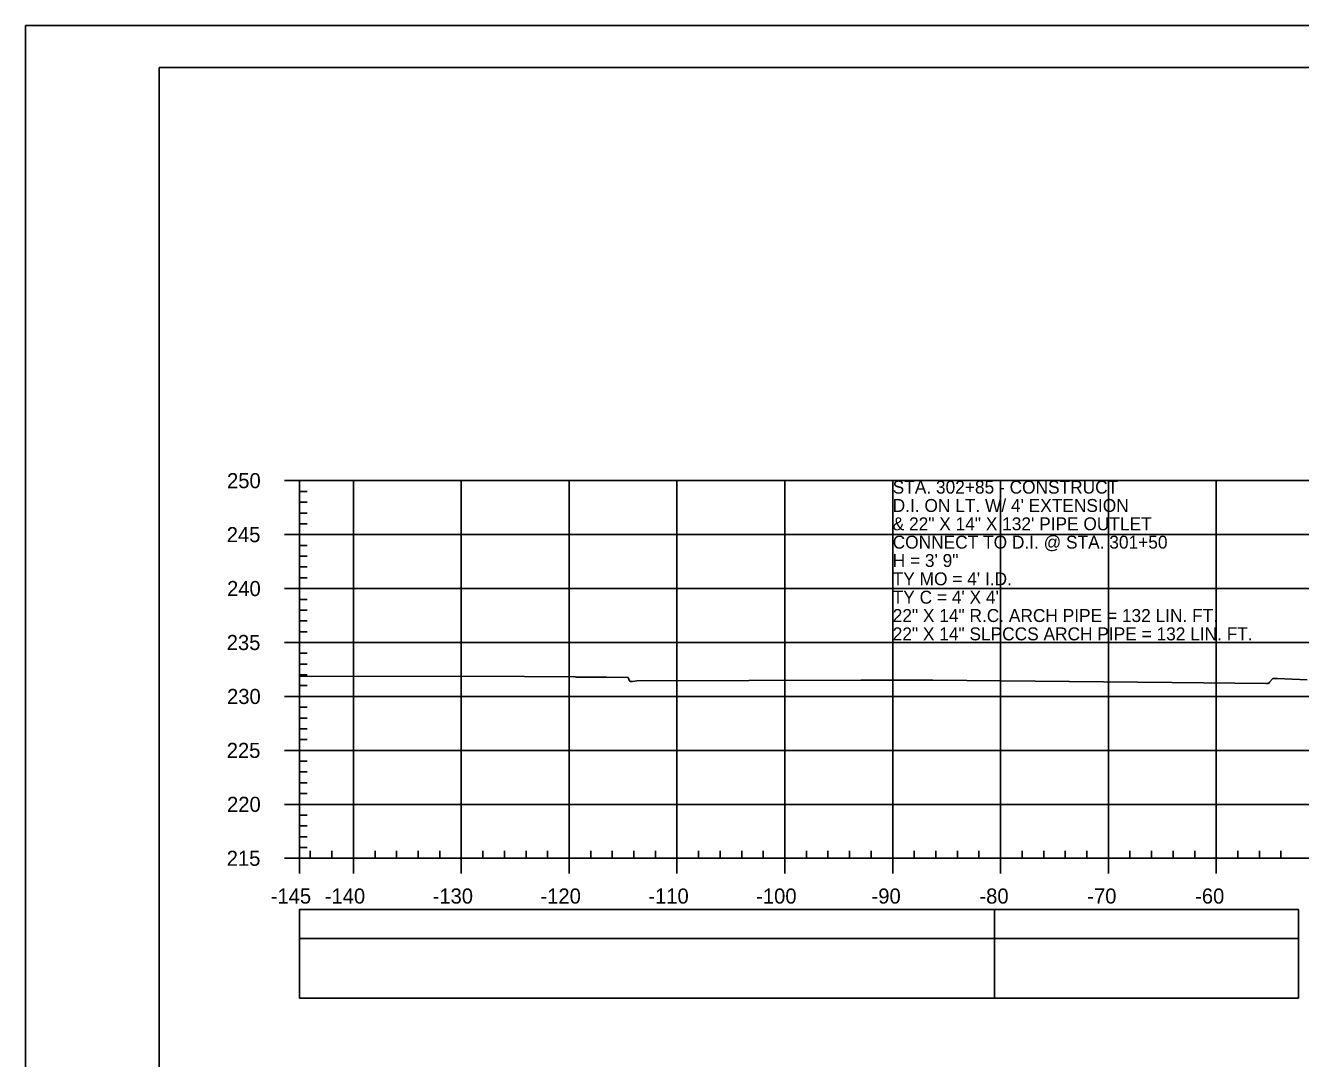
# Model space of a CAD drawing. Extents: x 1386544 to 1388153, y 379785 to 390999.
# Drawn here: x 1386544.5 to 1386662.7, y 384609.5 to 384705.3 of the extents above; entities that cross this region are included whole.
import ezdxf

# ---------------------------------------------------------------- set-up
doc = ezdxf.new("R2010")
doc.units = 0
for name, color, linetype in [('R_Axis', 7, 'Continuous'), ('R_Axis Annot', 7, 'Continuous'), ('R_Border', 7, 'Continuous'), ('R_Exist Surface', 7, 'Continuous'), ('R_Grid', 7, 'Continuous'), ('R_No Plot', 7, 'Continuous'), ('R_Striping', 7, 'Continuous'), ('R_Water Annot', 7, 'Continuous')]:
    doc.layers.add(name, color=color, linetype=linetype)

msp = doc.modelspace()

# ---------------------------------------------------------------- linework, layer by layer
at = {"layer": 'R_Axis'}
for p, q in [((1386568.47, 384663.09), (1386569.87, 384663.09)), ((1386569.87, 384628.09), (1386569.87, 384663.09)), ((1386569.87, 384662.09), (1386570.57, 384662.09)), ((1386569.87, 384661.09), (1386570.57, 384661.09)), ((1386569.87, 384660.09), (1386570.57, 384660.09)), ((1386568.47, 384658.09), (1386569.87, 384658.09)), ((1386569.87, 384659.09), (1386570.57, 384659.09)), ((1386569.87, 384657.09), (1386570.57, 384657.09)), ((1386569.87, 384656.09), (1386570.57, 384656.09)), ((1386569.87, 384655.09), (1386570.57, 384655.09)), ((1386569.87, 384654.09), (1386570.57, 384654.09)), ((1386568.47, 384653.09), (1386569.87, 384653.09)), ((1386569.87, 384652.09), (1386570.57, 384652.09)), ((1386569.87, 384651.09), (1386570.57, 384651.09)), ((1386569.87, 384650.09), (1386570.57, 384650.09)), ((1386569.87, 384649.09), (1386570.57, 384649.09)), ((1386568.47, 384648.09), (1386569.87, 384648.09)), ((1386569.87, 384647.09), (1386570.57, 384647.09)), ((1386569.87, 384646.09), (1386570.57, 384646.09)), ((1386569.87, 384645.09), (1386570.57, 384645.09)), ((1386569.87, 384644.09), (1386570.57, 384644.09)), ((1386568.47, 384643.09), (1386569.87, 384643.09)), ((1386569.87, 384642.09), (1386570.57, 384642.09)), ((1386569.87, 384641.09), (1386570.57, 384641.09)), ((1386569.87, 384640.09), (1386570.57, 384640.09)), ((1386569.87, 384639.09), (1386570.57, 384639.09)), ((1386568.47, 384638.09), (1386569.87, 384638.09)), ((1386569.87, 384637.09), (1386570.57, 384637.09)), ((1386569.87, 384636.09), (1386570.57, 384636.09)), ((1386569.87, 384635.09), (1386570.57, 384635.09)), ((1386569.87, 384634.09), (1386570.57, 384634.09)), ((1386568.47, 384633.09), (1386569.87, 384633.09)), ((1386569.87, 384632.09), (1386570.57, 384632.09)), ((1386569.87, 384631.09), (1386570.57, 384631.09)), ((1386569.87, 384630.09), (1386570.57, 384630.09)), ((1386569.87, 384629.09), (1386570.57, 384629.09)), ((1386569.87, 384628.09), (1386569.87, 384628.79)), ((1386570.87, 384628.09), (1386570.87, 384628.79)), ((1386572.87, 384628.09), (1386572.87, 384628.79)), ((1386576.87, 384628.09), (1386576.87, 384628.79)), ((1386578.87, 384628.09), (1386578.87, 384628.79)), ((1386580.87, 384628.09), (1386580.87, 384628.79)), ((1386582.87, 384628.09), (1386582.87, 384628.79)), ((1386586.87, 384628.09), (1386586.87, 384628.79)), ((1386588.87, 384628.09), (1386588.87, 384628.79)), ((1386590.87, 384628.09), (1386590.87, 384628.79)), ((1386592.87, 384628.09), (1386592.87, 384628.79)), ((1386596.87, 384628.09), (1386596.87, 384628.79)), ((1386598.87, 384628.09), (1386598.87, 384628.79)), ((1386600.87, 384628.09), (1386600.87, 384628.79)), ((1386602.87, 384628.09), (1386602.87, 384628.79)), ((1386606.87, 384628.09), (1386606.87, 384628.79)), ((1386608.87, 384628.09), (1386608.87, 384628.79)), ((1386610.87, 384628.09), (1386610.87, 384628.79)), ((1386612.87, 384628.09), (1386612.87, 384628.79)), ((1386616.87, 384628.09), (1386616.87, 384628.79)), ((1386618.87, 384628.09), (1386618.87, 384628.79)), ((1386620.87, 384628.09), (1386620.87, 384628.79)), ((1386622.87, 384628.09), (1386622.87, 384628.79)), ((1386626.87, 384628.09), (1386626.87, 384628.79)), ((1386628.87, 384628.09), (1386628.87, 384628.79)), ((1386630.87, 384628.09), (1386630.87, 384628.79)), ((1386632.87, 384628.09), (1386632.87, 384628.79)), ((1386636.87, 384628.09), (1386636.87, 384628.79)), ((1386638.87, 384628.09), (1386638.87, 384628.79)), ((1386640.87, 384628.09), (1386640.87, 384628.79)), ((1386642.87, 384628.09), (1386642.87, 384628.79)), ((1386646.87, 384628.09), (1386646.87, 384628.79)), ((1386648.87, 384628.09), (1386648.87, 384628.79)), ((1386650.87, 384628.09), (1386650.87, 384628.79)), ((1386652.87, 384628.09), (1386652.87, 384628.79)), ((1386656.87, 384628.09), (1386656.87, 384628.79)), ((1386658.87, 384628.09), (1386658.87, 384628.79)), ((1386660.87, 384628.09), (1386660.87, 384628.79)), ((1386568.47, 384628.09), (1386569.87, 384628.09)), ((1386569.87, 384628.09), (1386859.87, 384628.09)), ((1386569.87, 384626.69), (1386569.87, 384628.09)), ((1386574.87, 384626.69), (1386574.87, 384628.09)), ((1386584.87, 384626.69), (1386584.87, 384628.09)), ((1386594.87, 384626.69), (1386594.87, 384628.09)), ((1386604.87, 384626.69), (1386604.87, 384628.09)), ((1386614.87, 384626.69), (1386614.87, 384628.09)), ((1386624.87, 384626.69), (1386624.87, 384628.09)), ((1386634.87, 384626.69), (1386634.87, 384628.09)), ((1386644.87, 384626.69), (1386644.87, 384628.09)), ((1386654.87, 384626.69), (1386654.87, 384628.09))]:
    msp.add_line(p, q, dxfattribs=at)
at = {"layer": 'R_Axis Annot'}
for points in [[(1386569.87, 384620.64), (1386634.31, 384620.64), (1386634.31, 384623.35), (1386569.87, 384623.35)], [(1386569.87, 384615.12), (1386634.31, 384615.12), (1386634.31, 384620.64), (1386569.87, 384620.64)]]:
    msp.add_lwpolyline(points, close=True, dxfattribs=at)
at = {"layer": 'R_Border'}
for p, q in [((1386556.87, 384701.38), (1386873.05, 384701.38)), ((1386556.87, 384495.92), (1386556.87, 384701.38))]:
    msp.add_line(p, q, dxfattribs=at)
at = {"layer": 'R_Exist Surface'}
msp.add_lwpolyline([(1386569.87, 384644.98), (1386590.74, 384644.94), (1386595.45, 384644.91), (1386595.5, 384644.87), (1386598.32, 384644.87), (1386600.33, 384644.85), (1386600.43, 384644.61), (1386600.54, 384644.47), (1386600.74, 384644.49), (1386601.14, 384644.55), (1386621.91, 384644.59), (1386628.59, 384644.61), (1386650.74, 384644.39), (1386659.54, 384644.28), (1386659.68, 384644.29), (1386659.72, 384644.29), (1386659.82, 384644.4), (1386660.12, 384644.74), (1386660.22, 384644.74), (1386660.52, 384644.74), (1386663.3, 384644.62)], dxfattribs=at)
at = {"layer": 'R_Grid'}
for p, q in [((1386569.87, 384663.09), (1386859.87, 384663.09)), ((1386569.87, 384628.09), (1386569.87, 384663.09)), ((1386574.87, 384628.09), (1386574.87, 384663.09)), ((1386584.87, 384628.09), (1386584.87, 384663.09)), ((1386594.87, 384628.09), (1386594.87, 384663.09)), ((1386604.87, 384628.09), (1386604.87, 384663.09)), ((1386614.87, 384628.09), (1386614.87, 384663.09)), ((1386624.87, 384628.09), (1386624.87, 384663.09)), ((1386634.87, 384628.09), (1386634.87, 384663.09)), ((1386644.87, 384628.09), (1386644.87, 384663.09)), ((1386654.87, 384628.09), (1386654.87, 384663.09)), ((1386569.87, 384658.09), (1386859.87, 384658.09)), ((1386569.87, 384653.09), (1386859.87, 384653.09)), ((1386569.87, 384648.09), (1386859.87, 384648.09)), ((1386569.87, 384643.09), (1386859.87, 384643.09)), ((1386569.87, 384638.09), (1386859.87, 384638.09)), ((1386569.87, 384633.09), (1386859.87, 384633.09)), ((1386569.87, 384628.09), (1386859.87, 384628.09))]:
    msp.add_line(p, q, dxfattribs=at)
at = {"layer": 'R_No Plot'}
msp.add_line((1386544.47, 384705.28), (1386877.8, 384705.28), dxfattribs=at)
for points in [[(1386544.46, 384705.28), (1386877.8, 384705.28), (1386877.8, 384491.94), (1386544.46, 384491.94)], [(1386790.79, 384701.38), (1386810.41, 384701.38), (1386810.41, 384691.5), (1386826.52, 384691.5), (1386849.72, 384691.5), (1386849.72, 384667.17), (1386873.05, 384667.17), (1386873.05, 384495.92), (1386556.87, 384495.92), (1386556.87, 384701.38)]]:
    msp.add_lwpolyline(points, close=True, dxfattribs=at)
at = {"layer": 'R_Striping'}
for points in [[(1386634.31, 384620.65), (1386662.49, 384620.65), (1386662.49, 384623.35), (1386634.31, 384623.35)], [(1386634.31, 384615.13), (1386662.49, 384615.13), (1386662.49, 384620.65), (1386634.31, 384620.65)]]:
    msp.add_lwpolyline(points, close=True, dxfattribs=at)

# ---------------------------------------------------------------- texts
at = {"layer": 'R_Axis Annot'}
for s, p in [('250', (1386563.15, 384662.39)), ('245', (1386563.12, 384657.39)), ('240', (1386563.15, 384652.39)), ('235', (1386563.12, 384647.39)), ('230', (1386563.15, 384642.39)), ('225', (1386563.12, 384637.39)), ('220', (1386563.15, 384632.39)), ('215', (1386563.12, 384627.39)), ('-145', (1386567.2, 384623.89)), ('-140', (1386572.21, 384623.89)), ('-130', (1386582.21, 384623.89)), ('-120', (1386592.21, 384623.89)), ('-110', (1386602.21, 384623.89)), ('-100', (1386612.21, 384623.89)), ('-90', (1386622.91, 384623.89)), ('-80', (1386632.91, 384623.89)), ('-70', (1386642.91, 384623.89)), ('-60', (1386652.91, 384623.89))]:
    msp.add_text(s, height=1.4, dxfattribs=at).set_placement(p)
at = {"layer": 'R_Water Annot'}
for s, p in [('STA. 302+85 - CONSTRUCT', (1386624.87, 384661.89)), ("D.I. ON LT. W/ 4' EXTENSION", (1386624.87, 384660.19)), ('& 22" X 14" X 132\' PIPE OUTLET', (1386624.87, 384658.49)), ('CONNECT TO D.I. @ STA. 301+50', (1386624.87, 384656.79)), ('H = 3\' 9"', (1386624.87, 384655.09)), ("TY MO = 4' I.D.", (1386624.87, 384653.39)), ("TY C = 4' X 4'", (1386624.87, 384651.69)), ('22" X 14" R.C. ARCH PIPE = 132 LIN. FT.', (1386624.87, 384649.99)), ('22" X 14" SLPCCS ARCH PIPE = 132 LIN. FT.', (1386624.87, 384648.29))]:
    msp.add_text(s, height=1.2, dxfattribs=at).set_placement(p)

doc.saveas('drawing.dxf')
